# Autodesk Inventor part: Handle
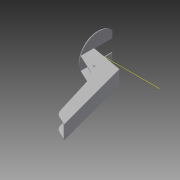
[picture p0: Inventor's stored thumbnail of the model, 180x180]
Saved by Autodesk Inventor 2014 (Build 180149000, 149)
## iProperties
Created: 2009-03
Part Number: Handle
Document SubType Name: Modeling
Designer: tangg
Density: 7.85 g/cm^3
Material: Steel
Mass: 68.364 g
Surface Area: 180.393 cm^2
Volume: 8.70879 cm^3
Appearance: Steel
Author: tangg
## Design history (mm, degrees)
sketch "Sketch1"
  geometry: L1 (0, -11.392)-(0, 0); L2 (35.824, -35.395)-(54.061, -95.007); L3 (0, -11.392)-(25.151, -23.12); L4 (62.066, -104.214)-(74.474, -110); L5 (74.474, -110)-(45, 0); L6 (0, 0)-(40.182, 0); L7 (0, 0)-(45, 0); L8 (45, 0)-(0, 8); L9 (0, 8)-(0, 0); L10 (27.142, 13.608)-(-2.758, 13.608) reference; A1 r 20 centre (16.699, -41.246) between (35.824, -35.395) and (25.151, -23.12); A2 r 15 centre (68.405, -90.619) between (54.061, -95.007) and (62.066, -104.214); 4 further points
  constraints: 20 end point, 4 point on circle, 4 point on line, 4 tangent, 2 centre point, 2 horizontal, 1 coincident, 1 parallel, 1 perpendicular, 1 vertical, 2 other
  dimensions: "d6" = 20 radius of A1; "d9" = 110 vertical distance of L4.end L5.end; "d10" = 15 radius of A2; "d11" = 105 deg angle of L5 L6; "d13" = 115 deg angle of L3 L1; "d14" = 45 distance of point (0, 0) L5.end; "d15" = 8 distance of L8.end point (0, 0); "d18" = 5.60779 distance from line of L8.end L10; "d19" = 25 distance from line of L1.start L10; "d29" = 15 vertical distance of point (23, -15) point (0, 0); "d30" = 23 horizontal distance of point (0, 0) point (23, -15)
extrude "Extrusion2" new body sketch "Sketch1" stored distance "d3" = 20; taper "d4" = 0 deg
fillet "Fillet1" dims "d25" = 2
shell "Shell2" dims "d5" = 1
sketch "Sketch2"
  geometry: L1 (-9.708, 3.608)-(-10.292, 3.608); L2 (-20, 19.392)-(-19, 19.392) reference; L3 (-20, 0)-(-19, 0) reference; L4 (-29.391, 46)-(-19, 46); L5 (-1, 1)-(-1, 19.392); L6 (-19, 1)-(-19, 5.494); L7 (-1, 46)-(9.391, 46); L8 (-19, 46)-(-1, 46); L9 (-20, 19.392)-(-20, 0) reference; L10 (-19, 19.392)-(-1, 19.392); L11 (-19, 19.392)-(-19, 46); L12 (-1, 19.392)-(-1, 46); L13 (-19, 5.494)-(-19, 19.392); L14 (-16, 19.392)-(-4, 19.392); L15 (-4, 19.392)-(-4, 9.392); L16 (-16, 9.392)-(-16, 19.392); L17 (-19, 0)-(-19, 19.392) reference; A1 r 22.394 centre (-10, 26) between (-10.292, 3.608) and (-9.708, 3.608); A2 r 27.857 centre (-10, 26) between (-29.391, 46) and (9.391, 46); A3 r 9 centre (-10, 19.392) between (-19, 19.392) and (-1, 19.392); 4 further points
  constraints: 27 end point, 17 perpendicular, 8 point on circle, 4 parallel, 3 centre point, 3 coincident, 2 midpoint, 1 horizontal, 1 point on line, 1 other
  dimensions: "d21" = 25 vertical distance of L5.start point (-10, 26); "d26" = 20 distance from line of L4 A1.centre; "d27" = 12 distance between parallel lines of L15 L16
extrude "Extrusion3" join sketch "Sketch2" distance "d7" = 1; taper "d8" = 0 deg
workaxis "Work Axis1"
sketch "Sketch3"
  geometry: C1 r 1.5 at (23, -15); 2 further points
  constraints: 1 centre point, 1 coincident
  dimensions: "d31" = 3 diameter of C1
extrude "Extrusion4" cut sketch "Sketch3" stored distance "d32" = 10; taper "d33" = 0 deg
body "Solid2"
